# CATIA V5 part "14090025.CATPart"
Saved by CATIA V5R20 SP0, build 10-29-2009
Part number: 14090025
Definition: NONE
Nomenclature: 14090025
Source: Unknown
Description: 14090025
Bounding box of the stored display mesh (mm): x -12.5 to 50, y -59 to 49.1, z -49.1 to 49.1
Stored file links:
  C:\Users\Utente\Desktop\IO LAVORO\3D X SITO CF\X SITO\PLASTICA\RF2\14090025.CATPart
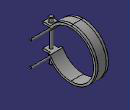
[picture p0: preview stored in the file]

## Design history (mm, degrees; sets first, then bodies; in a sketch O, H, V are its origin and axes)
Body1 "14090025" (main body)
  Solid1: solid without history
